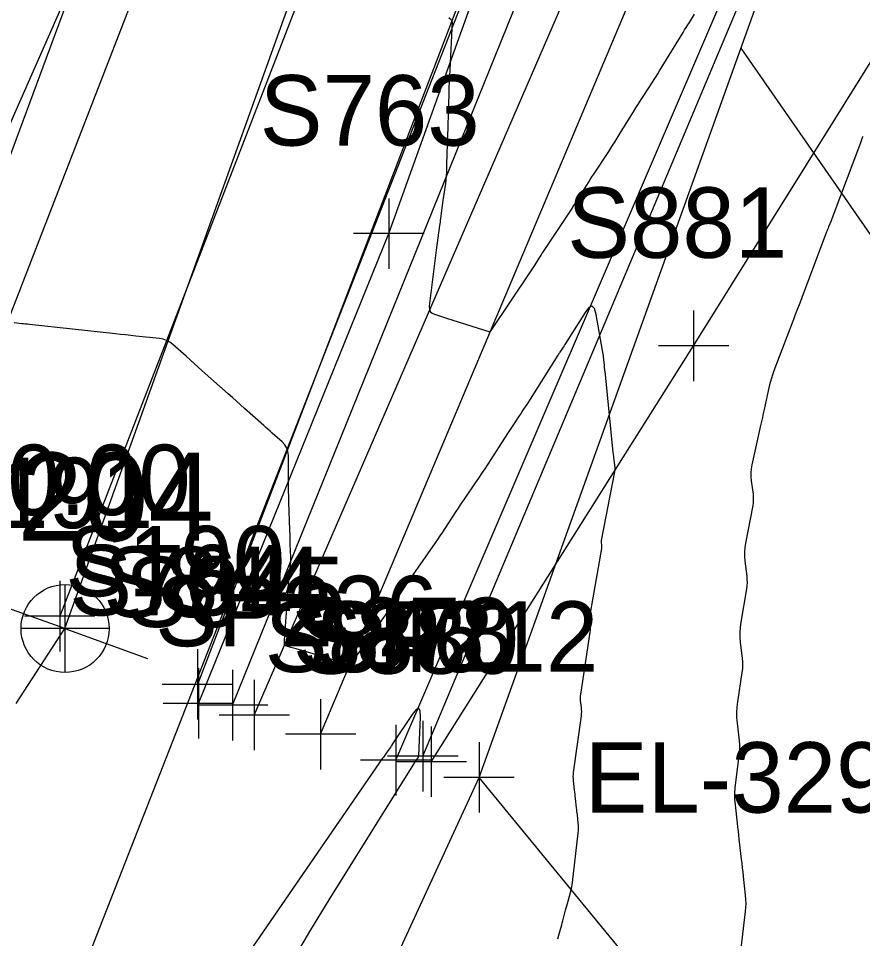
# Model space of a CAD drawing. Extents: x 816928 to 825690, y 436959 to 448212.
# Drawn here: x 818686.8 to 818734.8, y 444502.7 to 444555 of the extents above; entities that cross this region are included whole.
import ezdxf

# ---------------------------------------------------------------- set-up
doc = ezdxf.new("R2010")
doc.units = 0
for name, color, linetype in [('SURVEY - CENTERLINE - Preliminary', 7, 'Continuous'), ('SURVEY - CENTERLINE - Preliminary - Development', 7, 'Continuous'), ('SURVEY - CENTERLINE - Preliminary Text', 7, 'Continuous'), ('SURVEY - CONTOURS - Index with Text', 7, 'Continuous'), ('SURVEY - CONTOURS - Intermediate with optional Text', 7, 'Continuous'), ('SURVEY - DRAINAGE - Area Shapes', 7, 'Continuous'), ('SURVEY - DTM - Breaklines', 7, 'Continuous'), ('SURVEY - DTM - Breaklines - Points - Locators', 7, 'Continuous'), ('SURVEY - DTM - Breaklines - Points - Numbers', 7, 'Continuous'), ('SURVEY - NON-TRANSPORTATION - Features', 7, 'Continuous'), ('SURVEY - NON-TRANSPORTATION - Features - Points - Locators', 7, 'Continuous'), ('SURVEY - NON-TRANSPORTATION - Features - Points - Numbers', 7, 'Continuous'), ('SURVEY - NON-TRANSPORTATION - Features Text', 7, 'Continuous'), ('SURVEY - PROPERTY - ROW Lines', 7, 'Continuous'), ('SURVEY - PROPERTY - ROW Lines - Points - Elevations', 7, 'Continuous'), ('SURVEY - PROPERTY - ROW Lines - Points - Locators', 7, 'Continuous'), ('SURVEY - PROPERTY - ROW Lines - Points - Numbers', 7, 'Continuous'), ('SURVEY - PROPERTY - ROW Lines Text', 7, 'Continuous'), ('SURVEY - PROPERTY - Station and Offset Flags', 7, 'Continuous'), ('SURVEY - TRANSPORTATION - Roads', 7, 'Continuous'), ('SURVEY - TRANSPORTATION - Roads - Points - Locators', 7, 'Continuous'), ('SURVEY - TRANSPORTATION - Roads - Points - Numbers', 7, 'Continuous'), ('SURVEY - UTILITIES - Gas with Text', 7, 'Continuous'), ('SURVEY - UTILITIES - Water - Points - Locators', 7, 'Continuous'), ('SURVEY - UTILITIES - Water - Points - Numbers', 7, 'Continuous'), ('SURVEY - UTILITIES - Water with Text', 7, 'Continuous'), ('SURVEY - VEGETATION - Features with Text', 7, 'Continuous')]:
    doc.layers.add(name, color=color, linetype=linetype)

msp = doc.modelspace()

# ---------------------------------------------------------------- linework, layer by layer
at = {"layer": 'SURVEY - CENTERLINE - Preliminary'}
msp.add_line((818689.478, 444520.324), (818740.593, 444662.662), dxfattribs=at)
at = {"layer": 'SURVEY - CENTERLINE - Preliminary - Development'}
for p, q in [((818689.478, 444522.824), (818689.478, 444517.824)), ((818691.978, 444520.324), (818686.978, 444520.324))]:
    msp.add_line(p, q, dxfattribs=at)
at = {"layer": 'SURVEY - CENTERLINE - Preliminary Text'}
for q in [(818684.772, 444522.013), (818694.184, 444518.634), (818689.478, 444520.324)]:
    msp.add_line((818689.478, 444520.324), q, dxfattribs=at)
msp.add_circle((818689.497, 444520.33), 2.5, dxfattribs=at)
at = {"layer": 'SURVEY - CONTOURS - Index with Text'}
msp.add_lwpolyline([(818702.447, 444501.508), (818703.463, 444503.218), (818704.501, 444504.915), (818709.352, 444512.724), (818709.376, 444512.763), (818709.402, 444512.801), (818709.428, 444512.838), (818709.456, 444512.875), (818709.546, 444512.994), (818709.563, 444513.02), (818709.576, 444513.048), (818709.584, 444513.078), (818709.588, 444513.109), (818709.686, 444515.29), (818709.672, 444515.651), (818709.588, 444515.797), (818709.434, 444515.728), (818709.21, 444515.446), (818708.098, 444513.772), (818708.044, 444513.691), (818707.989, 444513.611), (818707.933, 444513.531), (818707.876, 444513.452), (818707.69, 444513.194), (818707.651, 444513.139), (818707.611, 444513.083), (818707.572, 444513.028), (818707.533, 444512.972), (818688.457, 444485.248)], dxfattribs=at)
at = {"layer": 'SURVEY - CONTOURS - Intermediate with optional Text'}
for points in [[(818711.287, 444555.041), (818711.418, 444554.923), (818711.442, 444554.896), (818711.459, 444554.866), (818711.469, 444554.833), (818711.471, 444554.797), (818711.339, 444552.074), (818711.324, 444551.733), (818711.31, 444551.393), (818711.298, 444551.052), (818711.288, 444550.711), (818711.255, 444549.524), (818711.249, 444549.322), (818711.242, 444549.12), (818711.235, 444548.918), (818711.227, 444548.717), (818711.201, 444548.058), (818711.196, 444547.917), (818711.191, 444547.775), (818711.187, 444547.634), (818711.185, 444547.493), (818711.166, 444546.475), (818711.159, 444546.258), (818711.145, 444546.041), (818711.124, 444545.824), (818711.096, 444545.608), (818710.957, 444544.649), (818710.937, 444544.508), (818710.917, 444544.366), (818710.898, 444544.225), (818710.88, 444544.083), (818710.821, 444543.62), (818710.808, 444543.521), (818710.795, 444543.422), (818710.782, 444543.323), (818710.768, 444543.223), (818710.573, 444541.816), (818710.532, 444541.514), (818710.492, 444541.212), (818710.454, 444540.91), (818710.418, 444540.608), (818710.183, 444538.641), (818710.186, 444538.479), (818710.237, 444538.348), (818710.335, 444538.248), (818710.482, 444538.179), (818711.038, 444538.004), (818711.158, 444537.967), (818711.277, 444537.929), (818711.396, 444537.892), (818711.515, 444537.855), (818713.623, 444537.193), (818713.632, 444537.192), (818713.639, 444537.193), (818713.646, 444537.197), (818713.652, 444537.203), (818713.675, 444537.237), (818713.676, 444537.239), (818713.677, 444537.24), (818713.678, 444537.242), (818713.679, 444537.244), (818713.683, 444537.25), (818713.684, 444537.251), (818713.685, 444537.252), (818713.685, 444537.253), (818713.686, 444537.255), (818715.893, 444540.54), (818715.968, 444540.653), (818716.042, 444540.767), (818716.116, 444540.881), (818716.188, 444540.995), (818716.424, 444541.371), (818716.474, 444541.451), (818716.526, 444541.531), (818716.577, 444541.611), (818716.63, 444541.69), (818718.107, 444543.916), (818718.25, 444544.134), (818718.392, 444544.353), (818718.533, 444544.573), (818718.672, 444544.795), (818719.122, 444545.519), (818719.219, 444545.674), (818719.317, 444545.829), (818719.416, 444545.983), (818719.516, 444546.136), (818720.368, 444547.435), (818720.55, 444547.714), (818720.73, 444547.994), (818720.908, 444548.275), (818721.083, 444548.558), (818721.773, 444549.677), (818721.918, 444549.911), (818722.064, 444550.144), (818722.212, 444550.375), (818722.361, 444550.606), (818722.85, 444551.359), (818722.954, 444551.521), (818723.057, 444551.683), (818723.159, 444551.846), (818723.26, 444552.01), (818724.591, 444554.189), (818724.679, 444554.332), (818724.768, 444554.475), (818724.858, 444554.617), (818724.949, 444554.759), (818725.246, 444555.221)], [(818734.8, 444548.273), (818734.772, 444548.202), (818734.681, 444547.972), (818734.661, 444547.922), (818734.642, 444547.873), (818734.623, 444547.823), (818734.604, 444547.774), (818733.156, 444543.913), (818733.116, 444543.808), (818733.076, 444543.703), (818733.035, 444543.599), (818732.994, 444543.494), (818732.858, 444543.153), (818732.829, 444543.079), (818732.801, 444543.006), (818732.773, 444542.932), (818732.745, 444542.859), (818731.412, 444539.318), (818731.364, 444539.19), (818731.315, 444539.062), (818731.265, 444538.935), (818731.215, 444538.808), (818731.05, 444538.393), (818731.015, 444538.304), (818730.98, 444538.215), (818730.946, 444538.125), (818730.912, 444538.036), (818729.811, 444535.119), (818729.699, 444534.805), (818729.599, 444534.487), (818729.51, 444534.166), (818729.432, 444533.842), (818729.197, 444532.777), (818729.147, 444532.548), (818729.097, 444532.32), (818729.047, 444532.092), (818728.996, 444531.864), (818728.506, 444529.637), (818728.466, 444529.408), (818728.446, 444529.178), (818728.446, 444528.947), (818728.466, 444528.716), (818728.566, 444527.958), (818728.581, 444527.796), (818728.582, 444527.634), (818728.571, 444527.473), (818728.546, 444527.312), (818728.135, 444525.188), (818728.095, 444524.93), (818728.077, 444524.672), (818728.078, 444524.413), (818728.101, 444524.153), (818728.207, 444523.303), (818728.223, 444523.121), (818728.226, 444522.939), (818728.215, 444522.758), (818728.191, 444522.577), (818727.868, 444520.694), (818727.83, 444520.412), (818727.812, 444520.13), (818727.816, 444519.846), (818727.84, 444519.563), (818727.952, 444518.635), (818727.969, 444518.437), (818727.972, 444518.238), (818727.962, 444518.04), (818727.939, 444517.842), (818727.682, 444516.165), (818727.646, 444515.862), (818727.63, 444515.559), (818727.635, 444515.256), (818727.66, 444514.952), (818727.776, 444513.958), (818727.794, 444513.745), (818727.799, 444513.533), (818727.79, 444513.32), (818727.767, 444513.108), (818727.562, 444511.608), (818727.528, 444511.287), (818727.514, 444510.966), (818727.52, 444510.645), (818727.546, 444510.324), (818727.665, 444509.273), (818727.69, 444509.048), (818727.716, 444508.823), (818727.741, 444508.598), (818727.766, 444508.373), (818727.895, 444507.23), (818727.923, 444506.985), (818727.951, 444506.74), (818727.978, 444506.495), (818728.006, 444506.251), (818728.127, 444505.177), (818728.146, 444504.946), (818728.152, 444504.716), (818728.145, 444504.486), (818728.124, 444504.256), (818727.414, 444498.286)], [(818717.488, 444502.704), (818717.636, 444503.256), (818717.668, 444503.375), (818717.7, 444503.493), (818717.731, 444503.611), (818717.763, 444503.73), (818717.924, 444504.329), (818717.958, 444504.458), (818717.993, 444504.586), (818718.027, 444504.715), (818718.062, 444504.843), (818718.213, 444505.406), (818718.243, 444505.527), (818718.269, 444505.649), (818718.29, 444505.772), (818718.307, 444505.896), (818718.642, 444508.705), (818718.654, 444508.848), (818718.659, 444508.99), (818718.655, 444509.132), (818718.643, 444509.275), (818718.591, 444509.74), (818718.58, 444509.839), (818718.568, 444509.939), (818718.557, 444510.039), (818718.546, 444510.138), (818718.484, 444510.682), (818718.471, 444510.799), (818718.458, 444510.915), (818718.445, 444511.032), (818718.432, 444511.149), (818718.371, 444511.689), (818718.361, 444511.805), (818718.359, 444511.92), (818718.364, 444512.036), (818718.376, 444512.152), (818718.818, 444515.367), (818718.831, 444515.488), (818718.836, 444515.608), (818718.833, 444515.729), (818718.823, 444515.849), (818718.777, 444516.244), (818718.77, 444516.328), (818718.768, 444516.413), (818718.773, 444516.497), (818718.783, 444516.581), (818719.325, 444520.123), (818719.335, 444520.209), (818719.34, 444520.294), (818719.338, 444520.38), (818719.331, 444520.466), (818719.297, 444520.747), (818719.292, 444520.807), (818719.291, 444520.867), (818719.295, 444520.927), (818719.303, 444520.986), (818719.971, 444524.883), (818719.977, 444524.928), (818719.98, 444524.973), (818719.98, 444525.018), (818719.976, 444525.063), (818719.957, 444525.21), (818719.954, 444525.241), (818719.954, 444525.273), (818719.956, 444525.304), (818719.961, 444525.335), (818720.714, 444529.224), (818720.723, 444529.276), (818720.728, 444529.327), (818720.729, 444529.38), (818720.728, 444529.432), (818720.717, 444529.603), (818720.714, 444529.639), (818720.711, 444529.676), (818720.707, 444529.712), (818720.703, 444529.749), (818720.663, 444530.06), (818720.654, 444530.127), (818720.646, 444530.194), (818720.639, 444530.26), (818720.632, 444530.327), (818720.179, 444534.76), (818720.165, 444534.896), (818720.151, 444535.031), (818720.137, 444535.166), (818720.123, 444535.301), (818720.078, 444535.743), (818720.068, 444535.838), (818720.055, 444535.932), (818720.041, 444536.026), (818720.025, 444536.12), (818719.66, 444538.166), (818719.562, 444538.503), (818719.424, 444538.635), (818719.247, 444538.564), (818719.03, 444538.289), (818717.923, 444536.523), (818717.88, 444536.456), (818717.837, 444536.389), (818717.793, 444536.322), (818717.749, 444536.255), (818717.603, 444536.038), (818717.572, 444535.992), (818717.541, 444535.945), (818717.511, 444535.898), (818717.481, 444535.851), (818715.715, 444533.065), (818715.609, 444532.898), (818715.501, 444532.733), (818715.392, 444532.568), (818715.282, 444532.404), (818714.919, 444531.871), (818714.842, 444531.756), (818714.765, 444531.641), (818714.689, 444531.526), (818714.614, 444531.409), (818713.504, 444529.676), (818713.328, 444529.404), (818713.151, 444529.135), (818712.971, 444528.866), (818712.789, 444528.6), (818712.19, 444527.731), (818712.063, 444527.544), (818711.937, 444527.357), (818711.812, 444527.168), (818711.688, 444526.979), (818711.06, 444526.01), (818710.925, 444525.803), (818710.788, 444525.598), (818710.649, 444525.393), (818710.508, 444525.19), (818709.245, 444523.382), (818709.146, 444523.24), (818709.048, 444523.096), (818708.951, 444522.952), (818708.855, 444522.807), (818708.544, 444522.332), (818708.476, 444522.231), (818708.408, 444522.13), (818708.339, 444522.03), (818708.269, 444521.93), (818706.117, 444518.897), (818706.104, 444518.879), (818706.091, 444518.861), (818706.079, 444518.843), (818706.067, 444518.825), (818706.027, 444518.765), (818706.018, 444518.752), (818706.01, 444518.739), (818706.001, 444518.726), (818705.992, 444518.714), (818705.769, 444518.405), (818705.717, 444518.35), (818705.658, 444518.317), (818705.591, 444518.306), (818705.516, 444518.318), (818702.616, 444519.171), (818702.539, 444519.193), (818702.462, 444519.216), (818702.385, 444519.238), (818702.309, 444519.26), (818702.037, 444519.339), (818701.999, 444519.355), (818701.973, 444519.38), (818701.958, 444519.413), (818701.954, 444519.454), (818701.959, 444519.6), (818701.96, 444519.632), (818701.962, 444519.663), (818701.964, 444519.694), (818701.966, 444519.726), (818701.987, 444519.978), (818701.991, 444520.032), (818701.995, 444520.086), (818701.999, 444520.14), (818702.002, 444520.194), (818702.084, 444521.515), (818702.103, 444521.798), (818702.124, 444522.081), (818702.148, 444522.364), (818702.175, 444522.646), (818702.306, 444523.988), (818702.314, 444524.092), (818702.318, 444524.196), (818702.319, 444524.3), (818702.315, 444524.405), (818702.297, 444524.745), (818702.293, 444524.819), (818702.29, 444524.892), (818702.288, 444524.965), (818702.286, 444525.038), (818702.277, 444525.519), (818702.275, 444525.622), (818702.272, 444525.726), (818702.269, 444525.829), (818702.266, 444525.932), (818702.211, 444527.486), (818702.201, 444527.819), (818702.193, 444528.152), (818702.188, 444528.485), (818702.185, 444528.818), (818702.18, 444530.155), (818702.157, 444530.378), (818702.092, 444530.581), (818701.983, 444530.764), (818701.83, 444530.928), (818701.263, 444531.432), (818701.141, 444531.54), (818701.02, 444531.648), (818700.898, 444531.756), (818700.777, 444531.864), (818699.693, 444532.831), (818699.461, 444533.038), (818699.229, 444533.245), (818698.997, 444533.452), (818698.764, 444533.659), (818697.288, 444534.974), (818697.057, 444535.18), (818696.826, 444535.386), (818696.595, 444535.592), (818696.365, 444535.798), (818695.612, 444536.473), (818695.444, 444536.602), (818695.262, 444536.701), (818695.067, 444536.769), (818694.858, 444536.807), (818693.512, 444536.946), (818693.223, 444536.977), (818692.935, 444537.007), (818692.646, 444537.038), (818692.358, 444537.069), (818687.477, 444537.6), (818687.366, 444537.612), (818687.255, 444537.624), (818687.145, 444537.636), (818687.034, 444537.648), (818686.609, 444537.694)]]:
    msp.add_lwpolyline(points, dxfattribs=at)
at = {"layer": 'SURVEY - DRAINAGE - Area Shapes'}
for p, q in [((818689.478, 444520.324), (818740.593, 444662.662)), ((818686.717, 444516.063), (818689.478, 444520.324))]:
    msp.add_line(p, q, dxfattribs=at)
at = {"layer": 'SURVEY - DTM - Breaklines'}
for points in [[(818676.308, 444526.27), (818695.981, 444570.723), (818712.39, 444618.98), (818728.83, 444665.288), (818745.895, 444712.28), (818764.807, 444759.048), (818784.52, 444806.667), (818801.14, 444861.811), (818818.983, 444900.087), (818838.243, 444946.217), (818855.869, 444992.165), (818873.704, 445038.582), (818892.288, 445085.577), (818894.59, 445096.559), (818896.482, 445123.312), (818901.189, 445133.745), (818919.534, 445174.233), (818947.165, 445168.058)], [(818958.139, 445160.069), (818932.682, 445121.487), (818907.758, 445078.468), (818886.279, 445033.29), (818867.243, 444986.881), (818848.651, 444941.091), (818830.333, 444893.785), (818812.367, 444847.898), (818794.091, 444801.186), (818775.412, 444755.123), (818757.321, 444708.609), (818740.17, 444661.598), (818740.227, 444661.382), (818723.384, 444614.358), (818707.23, 444567.59), (818689.196, 444521.032)], [(818699.004, 444515.979), (818718.173, 444563.389), (818729.639, 444600.536), (818750.328, 444657.749), (818757.231, 444663.397), (818768.514, 444660.989)], [(818700.242, 444515.417), (818720.602, 444562.453), (818733.805, 444599.01), (818753.55, 444656.663)], [(818704.011, 444514.326), (818723.819, 444561.346), (818737.049, 444598.03), (818756.086, 444655.819)], [(818708.283, 444512.852), (818728.042, 444558.974), (818743.07, 444595.846), (818758.891, 444648.726), (818761.156, 444654.784), (818766.903, 444655.166)], [(818710.286, 444512.763), (818725.189, 444536.39), (818742.384, 444563.975), (818759.621, 444596.785), (818770.905, 444614.352), (818781.667, 444628.297), (818796.529, 444628.496), (818828.121, 444604.14)]]:
    msp.add_lwpolyline(points, dxfattribs=at)
at = {"layer": 'SURVEY - DTM - Breaklines - Points - Locators'}
for p, q in [((818725.189, 444538.39), (818725.189, 444534.39)), ((818727.189, 444536.39), (818723.189, 444536.39)), ((818689.196, 444523.032), (818689.196, 444519.032)), ((818691.196, 444521.032), (818687.196, 444521.032)), ((818699.004, 444517.979), (818699.004, 444513.979)), ((818700.242, 444517.417), (818700.242, 444513.417)), ((818704.011, 444516.326), (818704.011, 444512.326)), ((818701.004, 444515.979), (818697.004, 444515.979)), ((818702.242, 444515.417), (818698.242, 444515.417)), ((818708.283, 444514.852), (818708.283, 444510.852)), ((818710.286, 444514.763), (818710.286, 444510.763)), ((818706.011, 444514.326), (818702.011, 444514.326)), ((818710.283, 444512.852), (818706.283, 444512.852)), ((818712.286, 444512.763), (818708.286, 444512.763))]:
    msp.add_line(p, q, dxfattribs=at)
at = {"layer": 'SURVEY - NON-TRANSPORTATION - Features'}
msp.add_lwpolyline([(818709.813, 444513.079), (818728.726, 444558.099), (818746.695, 444600.103), (818767.347, 444648.08), (818785.845, 444638.906), (818828.075, 444608.425)], dxfattribs=at)
at = {"layer": 'SURVEY - NON-TRANSPORTATION - Features - Points - Locators'}
for p, q in [((818709.813, 444515.079), (818709.813, 444511.079)), ((818711.813, 444513.079), (818707.813, 444513.079))]:
    msp.add_line(p, q, dxfattribs=at)
at = {"layer": 'SURVEY - PROPERTY - ROW Lines'}
for p, q in [((818713.007, 444511.874), (818764.01, 444653.9)), ((818692.885, 444468.204), (818713.007, 444511.874))]:
    msp.add_line(p, q, dxfattribs=at)
at = {"layer": 'SURVEY - PROPERTY - ROW Lines - Points - Locators'}
for p, q in [((818713.007, 444513.874), (818713.007, 444509.874)), ((818715.007, 444511.874), (818711.007, 444511.874))]:
    msp.add_line(p, q, dxfattribs=at)
at = {"layer": 'SURVEY - PROPERTY - ROW Lines Text'}
msp.add_lwpolyline([(818772.349, 444489.213), (818727.883, 444553.298)], dxfattribs=at)
at = {"layer": 'SURVEY - PROPERTY - Station and Offset Flags'}
msp.add_lwpolyline([(818732.902, 444487.636), (818713.007, 444511.874)], dxfattribs=at)
at = {"layer": 'SURVEY - TRANSPORTATION - Roads'}
for points in [[(818965.229, 445155.363), (818951.411, 445165.352), (818926.02, 445127.499), (818900.328, 445082.499), (818878.311, 445036.446), (818858.824, 444990.147), (818840.564, 444944.187), (818822.719, 444897.894), (818804.417, 444851.441), (818785.945, 444804.727), (818767.422, 444758.087), (818749.481, 444712.19), (818731.94, 444664.32), (818715.455, 444617.821), (818698.912, 444570.495), (818680.86, 444523.941)], [(818965.229, 445155.363), (818938.616, 445116.052), (818915.349, 445074.624), (818893.365, 445028.079), (818874.295, 444982.228), (818856.423, 444936.819), (818838.526, 444889.933), (818820.316, 444844.098), (818801.626, 444797.247), (818782.894, 444750.293), (818765.195, 444704.769), (818748.054, 444657.938), (818731.68, 444611.01), (818715.158, 444564.483), (818697.018, 444517.159)], [(818965.229, 445155.363), (818938.616, 445116.052), (818915.349, 445074.624), (818898.78, 445039.544), (818893.365, 445028.079), (818891.235, 445022.959), (818874.295, 444982.228), (818856.423, 444936.819), (818838.526, 444889.933), (818820.316, 444844.098), (818801.626, 444797.247), (818782.894, 444750.293), (818765.195, 444704.769), (818757.626, 444684.091), (818748.679, 444659.647), (818748.054, 444657.938), (818731.68, 444611.01), (818715.158, 444564.483), (818697.018, 444517.159)]]:
    msp.add_lwpolyline(points, dxfattribs=at)
at = {"layer": 'SURVEY - TRANSPORTATION - Roads - Points - Locators'}
for p, q in [((818697.018, 444519.159), (818697.018, 444515.159)), ((818699.018, 444517.159), (818695.018, 444517.159))]:
    msp.add_line(p, q, dxfattribs=at)
at = {"layer": 'SURVEY - UTILITIES - Gas with Text'}
msp.add_lwpolyline([(818677.986, 444524.549), (818704.191, 444595.26), (818728.998, 444664.068), (818764.629, 444758.415), (818803.581, 444855.269), (818837.396, 444944.843), (818872.359, 445029.489), (818905.906, 445097.999), (818946.069, 445164.692)], dxfattribs=at)
at = {"layer": 'SURVEY - UTILITIES - Water - Points - Locators'}
for p, q in [((818707.886, 444544.766), (818707.886, 444540.766)), ((818709.886, 444542.766), (818705.886, 444542.766)), ((818697.069, 444518.079), (818697.069, 444514.079)), ((818699.069, 444516.079), (818695.069, 444516.079))]:
    msp.add_line(p, q, dxfattribs=at)
at = {"layer": 'SURVEY - UTILITIES - Water with Text'}
msp.add_lwpolyline([(818697.069, 444516.079), (818707.886, 444542.766), (818724.217, 444588.304), (818740.773, 444636.214), (818757.106, 444682.286), (818774.671, 444727.707), (818803.235, 444799.745), (818822.09, 444847.157)], dxfattribs=at)
at = {"layer": 'SURVEY - VEGETATION - Features with Text'}
msp.add_line((818676.038, 444463.993), (818749.431, 444651.256), dxfattribs=at)

# ---------------------------------------------------------------- texts
at = {"layer": 'SURVEY - CENTERLINE - Preliminary - Development'}
msp.add_text('SP204', height=5, dxfattribs=at).set_placement((818677.868, 444525.324))
at = {"layer": 'SURVEY - DTM - Breaklines - Points - Numbers'}
for s, p in [('S881', (818718.011, 444541.39)), ('S191', (818682.018, 444526.032)), ('S844', (818691.668, 444520.979)), ('S845', (818692.906, 444520.417)), ('SP236', (818694.613, 444519.326)), ('S846', (818700.837, 444517.852)), ('S880', (818702.777, 444517.763))]:
    msp.add_text(s, height=4, dxfattribs=at).set_placement(p)
at = {"layer": 'SURVEY - NON-TRANSPORTATION - Features - Points - Numbers'}
msp.add_text('S878', height=4, dxfattribs=at).set_placement((818702.43, 444518.079))
at = {"layer": 'SURVEY - NON-TRANSPORTATION - Features Text'}
msp.add_text('3 STRAND BARBWIRE', height=5, rotation=71.1188, dxfattribs=at).set_placement((818667.386, 444541.341))
at = {"layer": 'SURVEY - PROPERTY - ROW Lines - Points - Elevations'}
for s, p in [('EL-320.00', (818671.949, 444526.773)), ('EL-329.00', (818719.007, 444509.874))]:
    msp.add_text(s, height=4, dxfattribs=at).set_placement(p)
at = {"layer": 'SURVEY - PROPERTY - ROW Lines - Points - Numbers'}
msp.add_text('SP212', height=4, dxfattribs=at).set_placement((818703.719, 444517.874))
at = {"layer": 'SURVEY - TRANSPORTATION - Roads - Points - Numbers'}
msp.add_text('S190', height=4, dxfattribs=at).set_placement((818689.509, 444522.159))
at = {"layer": 'SURVEY - UTILITIES - Water - Points - Numbers'}
for s, p in [('S763', (818700.55, 444547.766)), ('S764', (818689.734, 444521.079))]:
    msp.add_text(s, height=4, dxfattribs=at).set_placement(p)

doc.saveas('drawing.dxf')
